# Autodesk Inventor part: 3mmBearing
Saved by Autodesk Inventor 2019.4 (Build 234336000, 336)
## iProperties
Created: 2020-04
Part Number: 3mmBearing
Material: Generic
Document SubType Name: Modeling
Designer: Administrator
Density: 1 g/cm^3
Appearance: Default
Title: 3mmBearing v2
Author: Administrator
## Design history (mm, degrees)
feature "Body1"
body "Solid1"
